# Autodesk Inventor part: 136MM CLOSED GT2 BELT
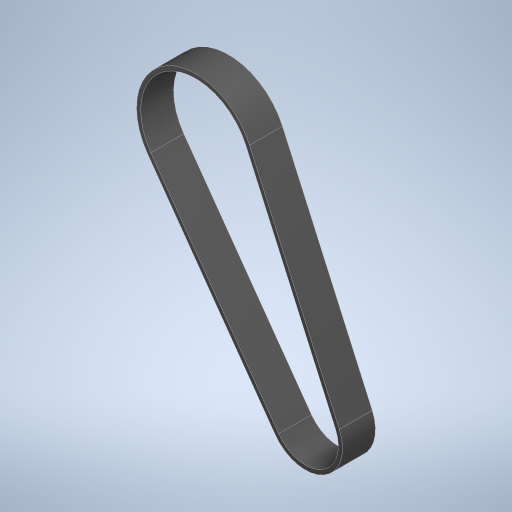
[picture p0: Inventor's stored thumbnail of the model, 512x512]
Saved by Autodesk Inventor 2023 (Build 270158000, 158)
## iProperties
Created: 2025-07
Part Number: 136MM CLOSED GT2 BELT
Material: Generic
Document SubType Name: Modeling
Designer: erjon
Density: 1 g/cm^3
Appearance: Default
Author: erjon
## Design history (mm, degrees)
feature "Base1"
body "Solid1"
